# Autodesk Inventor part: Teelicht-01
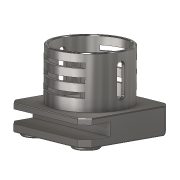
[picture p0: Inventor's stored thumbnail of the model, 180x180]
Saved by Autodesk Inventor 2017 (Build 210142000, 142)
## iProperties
Created: 2016-09
Part Number: Teelicht-01
Material: Generic
Document SubType Name: Modeling
Designer: e_krauts
Density: 1 g/cm^3
Appearance: Stahl - poliert
Author: e_krauts
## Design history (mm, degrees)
sketch "Skizze1"
  geometry: L1 (-29, -29)-(29, -29); L2 (29, -29)-(29, 29); L3 (29, 29)-(-29, 29); L4 (-29, 29)-(-29, -29); L5 (-29, -29)-(29, 29); L6 (29, -29)-(-29, 29); 1 further point
  constraints: 12 end point, 2 midpoint, 2 parallel, 1 horizontal, 1 perpendicular
  dimensions: "d0" = 58 distance of L3.end L2.end; "d1" = 58 distance of L2.end L1.end
extrude "Extrusion1" new body sketch "Skizze1" distance "d2" = 15; taper "d3" = 0 deg
sketch "Skizze2"
  geometry: L1 (-29, -29)-(-29, 29) reference; L2 (-29, 0)-(29, 0); L3 (29, 29)-(29, -29) reference; L4 (-29, 29)-(29, 29) reference; L5 (0, 29)-(0, -29); L6 (29, -29)-(-29, -29) reference; C1 r 7.5 at (0, 19); C2 r 7.5 at (-19, -19); C3 r 7.5 at (19, -19); 1 further point
  constraints: 4 end point, 4 midpoint, 3 centre point, 1 symmetric about line, 1 other
  dimensions: "d4" = 15 diameter of C1; "d5" = 15 diameter of C2; "d6" = 38 diameter of C1.centre L2; "d7" = 38 diameter of C2.centre L2; "d8" = 38 distance of C3.centre C2.centre
extrude "Extrusion2" join sketch "Skizze2" distance "d9" = 2; taper "d10" = 0 deg
chamfer "Fase1" distance "d11" = 0.5; stored, may be unused: second distance "d12" = 2, angle "d13" = 45 deg
sketch "Skizze3"
  geometry: C1 r 23 at (0, 0); C2 r 21 at (0, 0); 1 further point
  constraints: 2 centre point, 2 coincident
  dimensions: "d14" = 46 diameter of C1; "d15" = 42 diameter of C2
extrude "Extrusion3" join sketch "Skizze3" distance "d16" = 30; taper "d17" = 0 deg
sketch "Skizze4"
  geometry: L1 (58, -14.5)-(58, 0) reference; L2 (0, -10.75)-(58, -10.75); L3 (58, -10.75)-(58, -3.25); L4 (58, -3.25)-(0, -3.25); L5 (0, -3.25)-(0, -10.75); L6 (0, -10.75)-(58, -3.25); L7 (58, -10.75)-(0, -3.25); L8 (0, 0)-(58, 0) reference; 2 further points
  constraints: 12 end point, 2 midpoint, 2 parallel, 1 horizontal, 1 perpendicular, 1 point on line
  dimensions: "d18" = 7.5 distance of L3.end L2.end; "d19" = 7 distance from line of L8 point (29, -7)
extrude "Extrusion4" cut sketch "Skizze4" distance "d20" = 17; taper "d21" = 0 deg
chamfer "Fase2" distance "d22" = 5; stored, may be unused: second distance "d23" = 2, angle "d24" = 45 deg
chamfer "Fase3" distance "d25" = 0.5; stored, may be unused: second distance "d26" = 2, angle "d27" = 45 deg
workplane "Arbeitsebene1"
sketch "Skizze5"
  geometry: L1 (-23, 15)-(-23, 44.5) reference; L2 (23, 22)-(-23, 22); L3 (-23, 22)-(-23, 25); L4 (-23, 25)-(23, 25); L5 (23, 25)-(23, 22); L6 (23, 22)-(-23, 25); L7 (-23, 22)-(23, 25); L8 (23, 29.5)-(-23, 29.5); L9 (-23, 29.5)-(-23, 32.5); L10 (-23, 32.5)-(23, 32.5); L11 (23, 32.5)-(23, 29.5); L12 (23, 29.5)-(-23, 32.5); L13 (-23, 29.5)-(23, 32.5); L14 (23, 37)-(-23, 37); L15 (-23, 37)-(-23, 40); L16 (-23, 40)-(23, 40); L17 (23, 40)-(23, 37); L18 (23, 37)-(-23, 40); L19 (-23, 37)-(23, 40); L20 (-22.5, 45)-(22.5, 45) reference; 4 further points
  constraints: 36 end point, 6 midpoint, 6 parallel, 3 horizontal, 3 perpendicular, 3 point on line
  dimensions: "d29" = 3 distance between parallel lines of L14 L16; "d30" = 3 distance between parallel lines of L10 L8; "d31" = 3 distance between parallel lines of L4 L2; "d32" = 6.5 distance from line of point (0, 38.5) L20; "d33" = 14 distance from line of L20 point (0, 31); "d34" = 21.5 distance from line of point (0, 23.5) L20
extrude "Extrusion5" cut sketch "Skizze5" distance "d35" = 6; taper "d36" = 0 deg
mirror "Spiegeln1"
workplane "Arbeitsebene2"
sketch "Skizze6"
  geometry: L1 (0, 22.5)-(0, 37.5); L2 (2.5, 22.5)-(2.5, 37.5); L3 (-2.5, 37.5)-(-2.5, 22.5); L4 (-22.5, 45)-(22.5, 45) reference; A1 r 2.5 centre (0, 22.5) between (-2.5, 22.5) and (2.5, 22.5); A2 r 2.5 centre (0, 37.5) between (2.5, 37.5) and (-2.5, 37.5); 2 further points
  constraints: 8 end point, 4 point on circle, 4 tangent, 2 centre point, 1 midpoint, 1 parallel, 1 vertical
  dimensions: "d38" = 5 diameter of A2; "d39" = 15 distance of L1.start L1.end; "d40" = 7.5 distance from line of L1.end L4
extrude "Extrusion6" cut sketch "Skizze6" stored distance "d41" = 6; taper "d42" = 0 deg
sketch "Skizze7"
  geometry: L1 (1.45, -1.924)-(46.224, -1.924); L2 (46.224, -1.924)-(46.224, -12.657); L3 (46.224, -12.657)-(1.45, -12.657); L4 (1.45, -12.657)-(1.45, -1.924); 1 further point
  constraints: 2 other
feature "Prägen1" sketch "Skizze7" dims "d0" = 58, "d1" = 58, "d43" = 0.2, "d44" = 0
mirror "Spiegeln2"
node "Volumenkörper1"
other parameters: "d28" = -23, "d37" = 23
